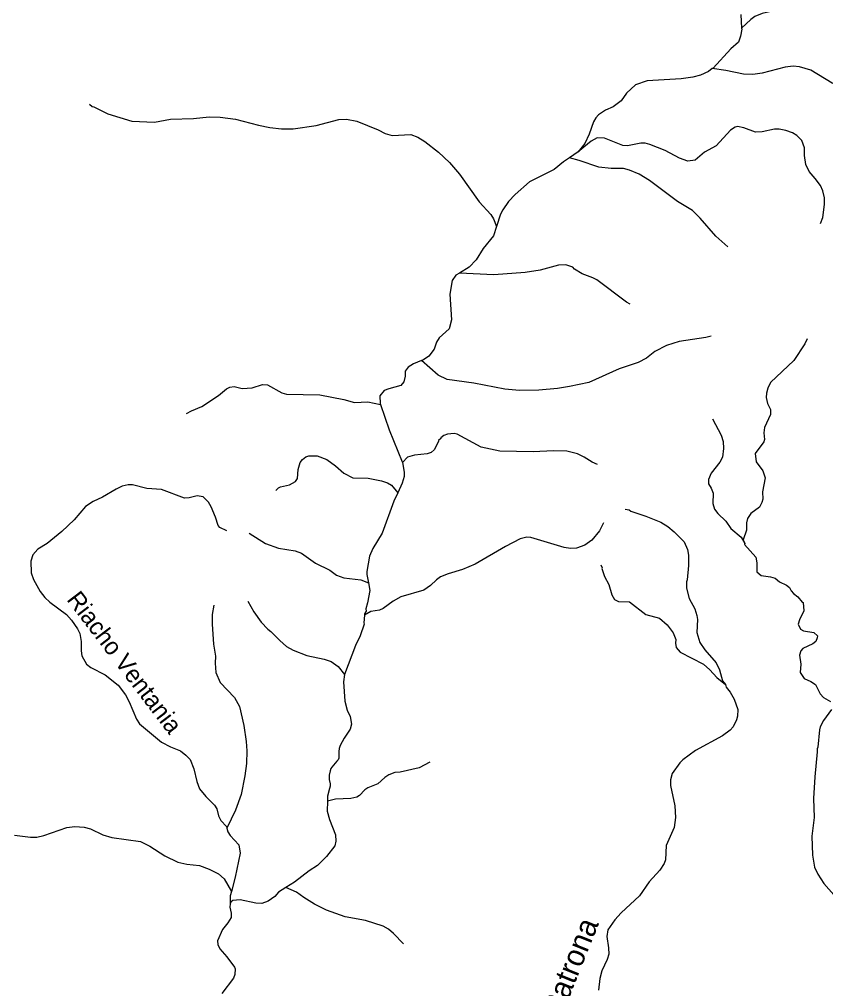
# Model space of a CAD drawing. Extents: x 280.4 to 335.6, y 8893.9 to 8949.5.
# Drawn here: x 309.86 to 317.28, y 8914.7 to 8923.61 of the extents above; entities that cross this region are included whole.
import ezdxf
from ezdxf.enums import TextEntityAlignment as Align

# ---------------------------------------------------------------- set-up
doc = ezdxf.new("R2010")
doc.units = 0
doc.header["$LTSCALE"] = 0.064
doc.layers.add('61', color=7, linetype='Continuous')
doc.layers.add('7', color=7, linetype='Continuous', lineweight=25)

msp = doc.modelspace()

# ---------------------------------------------------------------- linework, layer by layer
at = {"layer": '7'}
msp.add_line((315.0038, 8922.3919), (314.9226, 8922.3365), dxfattribs=at)
for points in [[(318.2696, 8923.6108), (318.1507, 8923.6545), (318.0716, 8923.6732), (318.0249, 8923.6714), (317.9296, 8923.6508), (317.878, 8923.655), (317.8286, 8923.6808), (317.7967, 8923.721), (317.7594, 8923.7882), (317.7156, 8923.8247), (317.6284, 8923.8297), (317.4736, 8923.79), (317.3994, 8923.7936), (317.3292, 8923.8101), (317.199, 8923.8539), (317.1357, 8923.8617), (317.1009, 8923.8561), (317.0392, 8923.8341), (316.8549, 8923.707), (316.7919, 8923.6847), (316.6943, 8923.6618), (316.6287, 8923.6338), (316.5896, 8923.6085), (316.5065, 8923.5293)], [(316.4992, 8923.6536), (316.5065, 8923.5293)], [(316.5065, 8923.5293), (316.507, 8923.5201), (316.4973, 8923.4547), (316.4762, 8923.3991), (316.4059, 8923.3366), (316.2439, 8923.1614), (316.2361, 8923.1554)], [(318.2147, 8923.0841), (318.0977, 8923.0719), (317.9808, 8923.0828), (317.8081, 8923.1276), (317.6546, 8923.1214), (317.6251, 8923.1149), (317.5852, 8923.0956), (317.5278, 8923.0333), (317.4875, 8923.0079), (317.3987, 8923.0014), (317.3398, 8923.0209), (317.1432, 8923.1407), (317.0391, 8923.1726), (316.9815, 8923.1772), (316.9068, 8923.1696), (316.695, 8923.1135), (316.608, 8923.1006), (316.5238, 8923.1061), (316.3617, 8923.1389), (316.2361, 8923.1554)], [(316.2361, 8923.1554), (316.2028, 8923.1299), (316.1282, 8923.0943), (316.0561, 8923.0763), (315.9493, 8923.0634), (315.6364, 8923.043), (315.5297, 8923.0073), (315.4481, 8922.9291), (315.3984, 8922.8589), (315.3253, 8922.8047), (315.2536, 8922.7748), (315.1911, 8922.7295), (315.1666, 8922.7036), (315.1449, 8922.6674), (315.1049, 8922.5542), (315.0654, 8922.4685), (315.0038, 8922.3919)], [(310.5061, 8922.8302), (310.5331, 8922.8068), (310.5488, 8922.8053), (310.6747, 8922.7392), (310.898, 8922.6721), (311.1048, 8922.664), (311.2536, 8922.6895), (311.464, 8922.6975), (311.6085, 8922.7121), (311.708, 8922.7105), (311.8518, 8922.6911), (312.0622, 8922.6353), (312.1677, 8922.6145), (312.2748, 8922.6031), (312.3803, 8922.6016), (312.5914, 8922.6321), (312.8025, 8922.6864), (312.8721, 8922.6895), (312.9666, 8922.6715), (313.1616, 8922.5942), (313.2272, 8922.5584), (313.2904, 8922.5394), (313.4623, 8922.5498), (313.5278, 8922.5263), (313.5925, 8922.486), (313.7184, 8922.3884), (313.8183, 8922.2935), (313.91, 8922.1857), (314.0912, 8921.9297), (314.1979, 8921.8147), (314.2248, 8921.7734), (314.2517, 8921.7029)], [(317.2324, 8921.7318), (317.2544, 8921.7869), (317.27, 8921.9049), (317.27, 8921.9676), (317.2525, 8922.0321), (317.2312, 8922.0807), (317.1833, 8922.1463), (317.127, 8922.2094), (317.0967, 8922.2733), (317.0846, 8922.3559), (317.0842, 8922.4261), (317.0588, 8922.4943), (317.0158, 8922.5401), (316.9742, 8922.5647), (316.9125, 8922.5875), (316.853, 8922.5993), (316.8096, 8922.5999), (316.6943, 8922.5744), (316.6342, 8922.5712), (316.5273, 8922.6128), (316.4671, 8922.6222), (316.4462, 8922.6163), (316.4033, 8922.5902), (316.2726, 8922.4453), (316.1635, 8922.3887), (316.0797, 8922.3131), (316.0131, 8922.3059), (315.9353, 8922.3323), (315.8035, 8922.4016), (315.6605, 8922.4594), (315.6189, 8922.4688), (315.578, 8922.4688), (315.4551, 8922.4467), (315.4135, 8922.4495), (315.2461, 8922.5165), (315.1777, 8922.5207), (315.1213, 8922.49), (315.0038, 8922.3919)], [(314.9226, 8922.3365), (314.8682, 8922.2994), (314.7833, 8922.228), (314.5539, 8922.1148), (314.4247, 8921.9983), (314.3631, 8921.9326), (314.3092, 8921.8579), (314.2888, 8921.8172), (314.2517, 8921.7029)], [(316.3803, 8921.5168), (316.2685, 8921.6137), (316.125, 8921.7795), (316.053, 8921.8499), (315.9156, 8921.9331), (315.6581, 8922.1276), (315.5636, 8922.1857), (315.4747, 8922.2223), (315.4209, 8922.2366), (315.3056, 8922.237), (315.1927, 8922.2486), (315.0119, 8922.312), (314.9226, 8922.3365)], [(314.2517, 8921.7029), (314.2237, 8921.6167), (314.1292, 8921.5028), (314.0653, 8921.3971), (314.0002, 8921.3307), (313.9121, 8921.2759)], [(315.4806, 8920.9906), (315.446, 8921.0079), (315.176, 8921.2122), (315.1376, 8921.2329), (315.0385, 8921.2688), (314.9678, 8921.3121), (314.9551, 8921.3285), (314.8881, 8921.3526), (314.8214, 8921.348), (314.6545, 8921.3031), (314.5146, 8921.2808), (314.2266, 8921.2583), (313.9121, 8921.2759)], [(313.9121, 8921.2759), (313.8785, 8921.255), (313.8447, 8921.2066), (313.8237, 8921.0807), (313.838, 8920.8455), (313.8158, 8920.7617), (313.7234, 8920.6812), (313.6999, 8920.6392), (313.6772, 8920.5755), (313.6298, 8920.51), (313.5798, 8920.4777), (313.5622, 8920.4708)], [(316.2269, 8920.6958), (316.1787, 8920.6819), (315.9313, 8920.6459), (315.8141, 8920.6102), (315.7093, 8920.5545), (315.6303, 8920.4937), (315.5556, 8920.4538), (315.3804, 8920.3964), (315.1013, 8920.2707), (314.924, 8920.2317), (314.8138, 8920.2151), (314.6417, 8920.1995), (314.4642, 8920.1963), (314.3272, 8920.2087), (314.0434, 8920.2632), (313.7973, 8920.297), (313.7153, 8920.3376), (313.5622, 8920.4708)], [(317.1089, 8920.6714), (317.0879, 8920.6254), (316.9859, 8920.4722), (316.7733, 8920.2687), (316.7483, 8920.2172), (316.7357, 8920.1724), (316.7328, 8920.1298), (316.7438, 8920.0759), (316.7709, 8920.02), (316.7711, 8919.975), (316.7167, 8919.8549), (316.7105, 8919.8067), (316.7166, 8919.7459), (316.7095, 8919.724), (316.632, 8919.6158), (316.6402, 8919.5396), (316.7015, 8919.4556), (316.7229, 8919.3916), (316.698, 8919.2628), (316.7005, 8919.1969), (316.6936, 8919.1662), (316.6696, 8919.1227), (316.5914, 8919.0633), (316.5608, 8919.0173), (316.5507, 8918.9775), (316.5503, 8918.9115), (316.5204, 8918.8209), (316.5353, 8918.7898)], [(313.5622, 8920.4708), (313.487, 8920.4412), (313.4383, 8920.4103), (313.4128, 8920.3728), (313.4108, 8920.3267), (313.3998, 8920.2754), (313.3709, 8920.2408), (313.2599, 8920.2124), (313.2175, 8920.1952), (313.1795, 8920.148), (313.181, 8920.0759), (313.184, 8920.0672)], [(311.4004, 8919.9841), (311.4445, 8920.009), (311.5406, 8920.0486), (311.695, 8920.1484), (311.7673, 8920.2097), (311.7996, 8920.2267), (311.839, 8920.2313), (311.9125, 8920.2139), (312.0027, 8920.2188), (312.0987, 8920.2506), (312.1458, 8920.2472), (312.2769, 8920.1755), (312.3212, 8920.1613), (312.6251, 8920.1546), (312.8469, 8920.1137), (312.9449, 8920.0862), (313.0679, 8920.0906), (313.184, 8920.0672)], [(313.184, 8920.0672), (313.2634, 8919.8352), (313.3851, 8919.5408), (313.3862, 8919.534)], [(316.2378, 8919.9355), (316.3178, 8919.7844), (316.336, 8919.7261), (316.341, 8919.6636), (316.3294, 8919.5815), (316.3045, 8919.5363), (316.2259, 8919.4362), (316.202, 8919.3773), (316.2004, 8919.3367), (316.2261, 8919.2977), (316.2431, 8919.2527), (316.2405, 8919.1569), (316.2568, 8919.1058), (316.2864, 8919.0634), (316.3605, 8918.9933), (316.4071, 8918.9259), (316.5024, 8918.8478), (316.5353, 8918.7898)], [(315.1796, 8919.515), (315.1308, 8919.5362), (315.0573, 8919.5841), (314.9953, 8919.6144), (314.8993, 8919.6381), (314.7763, 8919.6414), (314.5873, 8919.6302), (314.2826, 8919.6366), (314.1093, 8919.6753), (313.8908, 8919.794), (313.8611, 8919.7995), (313.8014, 8919.7927), (313.7657, 8919.7808), (313.7399, 8919.7616), (313.7382, 8919.7529), (313.7187, 8919.7374), (313.7191, 8919.7255), (313.6773, 8919.6508), (313.6517, 8919.6252), (313.6141, 8919.6126), (313.4975, 8919.5995), (313.4335, 8919.5827), (313.3862, 8919.534)], [(312.2213, 8919.2764), (312.245, 8919.3002), (312.2659, 8919.3106), (312.3481, 8919.3297), (312.4015, 8919.358), (312.4209, 8919.3868), (312.4258, 8919.4689), (312.4452, 8919.5325), (312.4671, 8919.5623), (312.4979, 8919.5853), (312.5241, 8919.595), (312.6025, 8919.5942), (312.6898, 8919.5597), (312.7692, 8919.504), (312.8464, 8919.4348), (312.9289, 8919.3935), (313.0697, 8919.3902), (313.1945, 8919.3663), (313.2483, 8919.3478), (313.2847, 8919.3262), (313.3441, 8919.2551)], [(313.3862, 8919.534), (313.4014, 8919.4439), (313.4014, 8919.4044), (313.3838, 8919.3423), (313.3441, 8919.2551)], [(311.77, 8918.9061), (311.7049, 8918.9365), (311.6908, 8918.9535), (311.6667, 8919.0307), (311.6254, 8919.1266), (311.6013, 8919.1675), (311.5518, 8919.2191), (311.4974, 8919.2255), (311.4248, 8919.2087), (311.3802, 8919.2067), (311.1705, 8919.2847), (311.0338, 8919.2946), (310.9025, 8919.3292), (310.8628, 8919.3276), (310.8091, 8919.315), (310.7516, 8919.2894), (310.6279, 8919.2142), (310.5415, 8919.174), (310.4701, 8919.1279), (310.366, 8919.0065), (310.2544, 8918.8976), (310.1167, 8918.7886), (310.0318, 8918.7377), (309.9849, 8918.6851), (309.9664, 8918.6268), (309.971, 8918.5177), (309.9911, 8918.4572), (310.0536, 8918.3463), (310.0958, 8918.2932), (310.1422, 8918.2484), (310.2957, 8918.1364), (310.3425, 8918.0847), (310.3979, 8918.0052), (310.4172, 8917.9605), (310.4313, 8917.8884), (310.4317, 8917.8012), (310.4382, 8917.7559), (310.4808, 8917.6778), (310.5189, 8917.6494), (310.6501, 8917.5818), (310.7707, 8917.4855), (310.8382, 8917.3969), (310.8736, 8917.3322), (310.9408, 8917.1724), (310.9687, 8917.131), (311.1701, 8916.9607), (311.2523, 8916.9184), (311.3432, 8916.881), (311.3949, 8916.842), (311.4334, 8916.8014), (311.4677, 8916.7169), (311.4934, 8916.5989), (311.5199, 8916.5338), (311.5776, 8916.4607), (311.6566, 8916.3836), (311.6774, 8916.3484), (311.693, 8916.2827), (311.7143, 8916.2398), (311.7669, 8916.1875), (311.7717, 8916.1699)], [(313.3441, 8919.2551), (313.3085, 8919.1769), (313.2005, 8918.8832), (313.114, 8918.7416), (313.0835, 8918.6712), (313.0578, 8918.5306), (313.0576, 8918.5023), (313.0731, 8918.4264)], [(315.4359, 8919.1054), (315.4705, 8919.0985), (315.4876, 8919.0864), (315.6267, 8919.0414), (315.7619, 8918.9855), (315.8291, 8918.944), (315.8867, 8918.896), (315.9779, 8918.8041), (316.0093, 8918.7344), (316.0162, 8918.6826), (316.0162, 8918.5858), (316.0066, 8918.4559), (316.0003, 8918.4363), (316.0004, 8918.3788), (316.024, 8918.2842), (316.0751, 8918.1883), (316.0955, 8918.1265), (316.0993, 8918.0909), (316.0932, 8917.9709), (316.1223, 8917.8767), (316.1678, 8917.8108), (316.2713, 8917.6903), (316.3015, 8917.6262), (316.3311, 8917.5259), (316.3578, 8917.4925)], [(315.2346, 8918.9782), (315.2001, 8918.9042), (315.1276, 8918.82), (315.0647, 8918.7746), (314.9888, 8918.7457), (314.9319, 8918.7426), (314.8738, 8918.7507), (314.5659, 8918.8452), (314.5291, 8918.8481), (314.4687, 8918.8323), (314.3347, 8918.7624), (314.0539, 8918.5978), (313.9393, 8918.5494), (313.8062, 8918.509), (313.7373, 8918.481), (313.7, 8918.4557), (313.6455, 8918.4031), (313.5822, 8918.3604), (313.3719, 8918.2982), (313.3001, 8918.2575), (313.208, 8918.1901), (313.1742, 8918.1753), (313.095, 8918.1637), (313.036, 8918.1298)], [(311.9751, 8918.8833), (312.1262, 8918.7883), (312.2459, 8918.7456), (312.3987, 8918.7201), (312.4564, 8918.6999), (312.5876, 8918.6092), (312.7171, 8918.5434), (312.7801, 8918.496), (312.8466, 8918.4739), (313.0036, 8918.4536), (313.0731, 8918.4264)], [(316.5353, 8918.7898), (316.5328, 8918.7792), (316.6368, 8918.6618), (316.6463, 8918.6098), (316.6471, 8918.5266), (316.6872, 8918.4938), (316.7727, 8918.4836), (316.8146, 8918.4709), (316.8552, 8918.4375), (316.9207, 8918.4054), (316.9472, 8918.3834), (316.9616, 8918.354), (316.9827, 8918.3296), (317.0228, 8918.299), (317.0628, 8918.2497), (317.0717, 8918.2474), (317.078, 8918.1691), (317.0395, 8918.0877), (317.0273, 8918.0482), (317.0475, 8917.9996), (317.075, 8917.9863), (317.1704, 8917.9701), (317.2029, 8917.9398), (317.2028, 8917.9221), (317.1903, 8917.8873), (317.1606, 8917.8658), (317.0688, 8917.8226), (317.0523, 8917.8014), (317.0398, 8917.762), (317.0508, 8917.6798), (317.0462, 8917.6036), (317.0823, 8917.5477), (317.1446, 8917.521), (317.1857, 8917.4911), (317.2291, 8917.4066), (317.2594, 8917.3738), (317.3244, 8917.3348)], [(315.2115, 8918.5917), (315.225, 8918.5656), (315.2205, 8918.5589), (315.2463, 8918.486), (315.2843, 8918.4102), (315.3123, 8918.317), (315.3383, 8918.2741), (315.3741, 8918.2563), (315.4761, 8918.2526), (315.6254, 8918.1353), (315.7512, 8918.1024), (315.8211, 8918.0404), (315.8779, 8917.9686), (315.9009, 8917.9068), (315.8981, 8917.8734), (315.9042, 8917.8321), (315.9406, 8917.7884), (316.1552, 8917.678), (316.2153, 8917.6271), (316.2793, 8917.5554), (316.3578, 8917.4925)], [(313.0731, 8918.4264), (313.0874, 8918.3568), (313.066, 8918.2435), (313.0486, 8918.1872), (313.0539, 8918.1653), (313.037, 8918.143), (313.036, 8918.1298)], [(311.6511, 8918.221), (311.6344, 8918.1358), (311.6344, 8918.0454), (311.6471, 8917.8633), (311.6661, 8917.7533), (311.6633, 8917.6873), (311.6692, 8917.6017), (311.7083, 8917.5107), (311.8426, 8917.3734), (311.8885, 8917.2887), (311.9267, 8917.1145), (311.9493, 8916.9682), (311.9557, 8916.8819), (311.9508, 8916.7659), (311.9378, 8916.6508), (311.9029, 8916.4804), (311.8502, 8916.3357), (311.7717, 8916.1699)], [(311.9649, 8918.2573), (312.0206, 8918.16), (312.0878, 8918.065), (312.1466, 8918.0017), (312.1753, 8917.9809), (312.2571, 8917.896), (312.3197, 8917.8412), (312.3802, 8917.8083), (312.5075, 8917.7575), (312.6667, 8917.724), (312.7306, 8917.7033), (312.7944, 8917.656), (312.8527, 8917.583)], [(313.036, 8918.1298), (313.0308, 8918.0597), (313.0347, 8918.0455)], [(313.0347, 8918.0455), (312.9971, 8917.9388), (312.955, 8917.851), (312.8527, 8917.583)], [(312.8527, 8917.583), (312.8454, 8917.5171), (312.8563, 8917.3393), (312.8765, 8917.2552), (312.9054, 8917.1967), (312.9185, 8917.1262), (312.9054, 8917.0805), (312.8498, 8916.9977), (312.8144, 8916.9298), (312.8047, 8916.9042), (312.802, 8916.8746), (312.7998, 8916.8156), (312.7946, 8916.7978), (312.7836, 8916.7863), (312.7374, 8916.7315), (312.7274, 8916.718), (312.7207, 8916.6979), (312.7135, 8916.6585), (312.7122, 8916.6186), (312.7207, 8916.5799), (312.7211, 8916.5585), (312.7151, 8916.5343), (312.6962, 8916.4649), (312.6957, 8916.4197)], [(316.3578, 8917.4925), (316.3645, 8917.4688), (316.401, 8917.4217), (316.4381, 8917.3564), (316.4704, 8917.2625), (316.4673, 8917.2), (316.4594, 8917.168), (316.4287, 8917.1034), (316.4018, 8917.0734), (316.3291, 8917.0213), (316.0828, 8916.8838), (315.9658, 8916.7998), (315.9376, 8916.7714), (315.8678, 8916.6744), (315.8534, 8916.6146), (315.8516, 8916.5619), (315.893, 8916.3748), (315.8995, 8916.2685), (315.8848, 8916.1775), (315.8136, 8916.011), (315.8051, 8915.879), (315.7941, 8915.8469), (315.7528, 8915.783), (315.6569, 8915.6768), (315.5678, 8915.5499), (315.3969, 8915.3933), (315.3409, 8915.3275), (315.2771, 8915.2354), (315.2679, 8915.1739), (315.2821, 8915.069), (315.2835, 8915.0108), (315.2693, 8914.9636), (315.2199, 8914.8579), (315.2025, 8914.7882), (315.1907, 8914.6809)], [(317.333, 8917.2631), (317.2595, 8917.161), (317.2304, 8917.104), (317.2222, 8917.0738), (317.2061, 8916.9152), (317.2, 8916.9017), (317.2028, 8916.8723), (317.1789, 8916.642), (317.1679, 8916.4428), (317.1741, 8916.2693), (317.1534, 8916.0973), (317.1582, 8915.9223), (317.1783, 8915.8107), (317.207, 8915.7489), (317.263, 8915.6626), (317.4939, 8915.4017)], [(313.6382, 8916.7781), (313.5393, 8916.7254), (313.3639, 8916.686), (313.3171, 8916.6824), (313.2624, 8916.6603), (313.2252, 8916.6375), (313.1602, 8916.5796), (313.0689, 8916.5419), (313.0408, 8916.5233), (312.99, 8916.4714), (312.9653, 8916.4554), (312.9105, 8916.4429), (312.7697, 8916.4364), (312.6957, 8916.4197)], [(312.6957, 8916.4197), (312.6947, 8916.3267), (312.7142, 8916.2519), (312.7712, 8916.1085), (312.773, 8916.0526), (312.7648, 8916.0086), (312.6887, 8915.9092), (312.6045, 8915.8267), (312.5275, 8915.7774), (312.394, 8915.6732), (312.3145, 8915.624)], [(309.8183, 8916.1068), (309.9654, 8916.0877), (310.0215, 8916.0877), (310.0869, 8916.1024), (310.2998, 8916.1772), (310.3715, 8916.1854), (310.4588, 8916.1786), (310.5155, 8916.1642), (310.6293, 8916.1104), (310.712, 8916.0841), (310.977, 8916.0471), (311.0632, 8916.0038), (311.2015, 8915.9173), (311.3208, 8915.8575), (311.4029, 8915.8405), (311.5207, 8915.8289), (311.6094, 8915.7948), (311.695, 8915.7519), (311.7473, 8915.7044), (311.8124, 8915.5879)], [(311.7717, 8916.1699), (311.7808, 8916.1368), (311.8028, 8916.1023), (311.8806, 8916.0182), (311.8931, 8915.9397), (311.8486, 8915.7216), (311.8124, 8915.5879)], [(312.3145, 8915.624), (312.2475, 8915.5825), (312.213, 8915.5412), (312.1518, 8915.4989), (312.0941, 8915.4769), (312.038, 8915.4815), (311.8926, 8915.512), (311.8268, 8915.5052), (311.8102, 8915.4926), (311.8016, 8915.475)], [(313.3967, 8915.1062), (313.3051, 8915.202), (313.2575, 8915.2417), (313.2095, 8915.2704), (313.0466, 8915.3221), (312.859, 8915.3565), (312.6884, 8915.4166), (312.5772, 8915.4724), (312.4787, 8915.5333), (312.4129, 8915.5827), (312.3145, 8915.624)], [(311.8124, 8915.5879), (311.8016, 8915.5481), (311.8016, 8915.475)], [(311.8016, 8915.475), (311.7993, 8915.4437), (311.8118, 8915.3889), (311.8102, 8915.348), (311.7814, 8915.2994), (311.7303, 8915.2385), (311.6857, 8915.1333), (311.6895, 8915.1015), (311.7064, 8915.0611), (311.7723, 8914.9868), (311.842, 8914.894), (311.8482, 8914.8765), (311.8457, 8914.8262), (311.8321, 8914.792), (311.7255, 8914.6495)]]:
    msp.add_lwpolyline(points, dxfattribs=at)

# ---------------------------------------------------------------- texts
at = {"layer": '61'}
for s, height, rotation, p in [('Riacho Ventania', 0.16, 307.304, (310.7677, 8917.6479)), ('Córrego Patrona', 0.2, 68.098, (314.8262, 8914.3764))]:
    msp.add_text(s, height=height, rotation=rotation, dxfattribs=at).set_placement(p, align=Align.CENTER)

doc.saveas('drawing.dxf')
